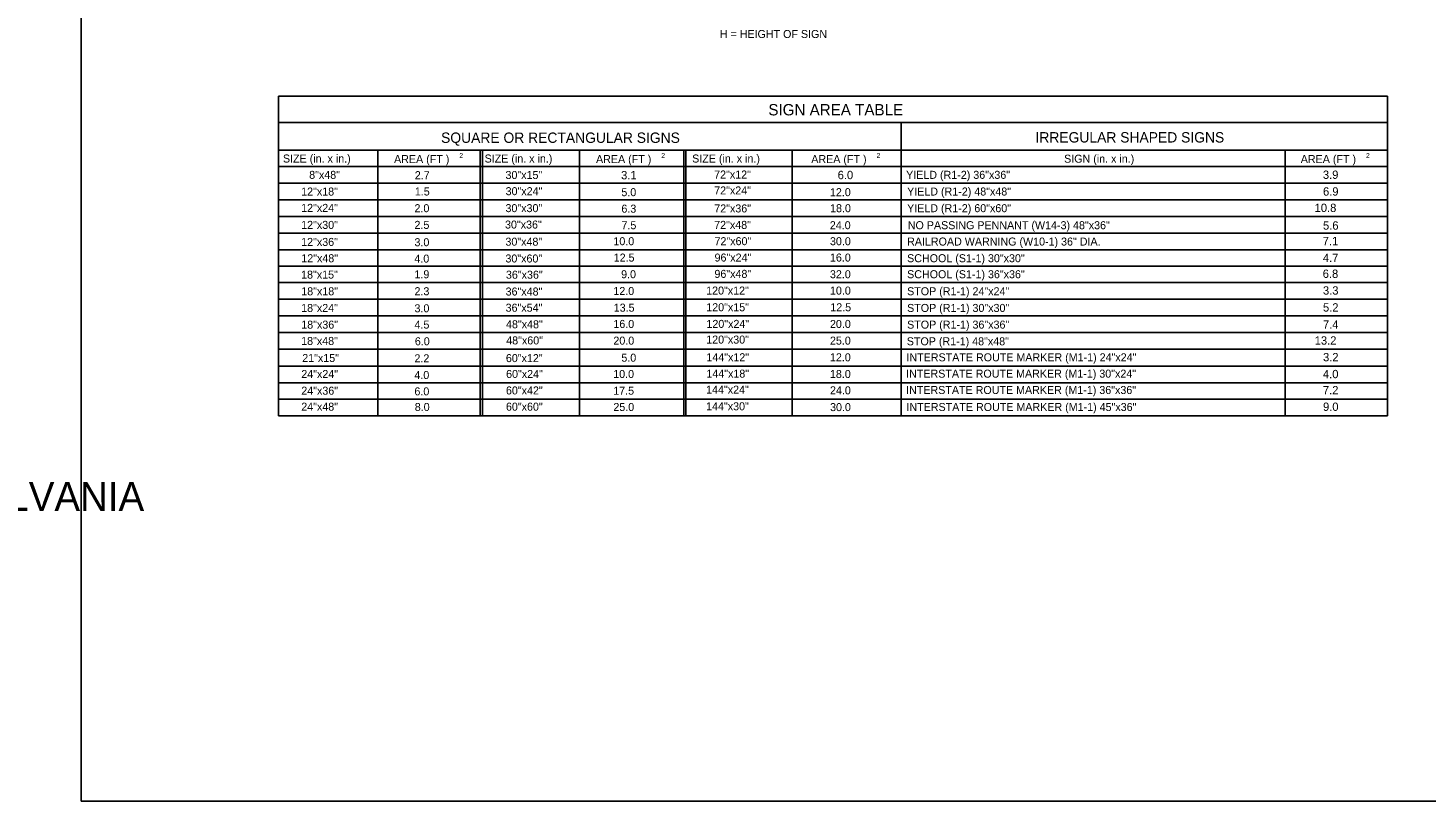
# Model space of a CAD drawing. Extents: x 644358 to 648627, y 294594 to 295782.
# Drawn here: x 645219 to 645743, y 295203 to 295492 of the extents above; entities that cross this region are included whole.
import ezdxf

# ---------------------------------------------------------------- set-up
doc = ezdxf.new("R2010")
doc.units = 0
for name, color, linetype in [('1', 7, 'Continuous'), ('2', 7, 'Continuous'), ('4', 7, 'Continuous')]:
    doc.layers.add(name, color=color, linetype=linetype)

msp = doc.modelspace()

# ---------------------------------------------------------------- linework, layer by layer
at = {"layer": '1'}
for p, q in [((645239.31, 295766.63), (645239.31, 295202.63)), ((646025.31, 295202.63), (645239.31, 295202.63)), ((645239.31, 295202.63), (645825.31, 295202.63))]:
    msp.add_line(p, q, dxfattribs=at)
at = {"layer": '2'}
for p, q in [((645313.28, 295466.78), (645313.28, 295347.03)), ((645729.03, 295466.78), (645313.28, 295466.78)), ((645729.03, 295347.03), (645729.03, 295466.78)), ((645729.03, 295456.9), (645313.28, 295456.9)), ((645546.65, 295456.9), (645546.65, 295347.03)), ((645313.28, 295446.53), (645729.03, 295446.53)), ((645350.53, 295446.53), (645350.53, 295347.03)), ((645388.9, 295446.53), (645388.9, 295347.03)), ((645389.78, 295446.53), (645389.78, 295347.03)), ((645426.08, 295446.53), (645426.08, 295347.03)), ((645465.28, 295446.53), (645465.28, 295347.03)), ((645466.03, 295446.53), (645466.03, 295347.03)), ((645505.78, 295446.53), (645505.78, 295347.03)), ((645690.65, 295347.03), (645690.65, 295446.53)), ((645313.28, 295440.4), (645729.03, 295440.4)), ((645313.28, 295434.15), (645729.03, 295434.15)), ((645313.28, 295427.9), (645729.03, 295427.9)), ((645313.28, 295421.65), (645729.03, 295421.65)), ((645313.28, 295415.4), (645729.03, 295415.4)), ((645313.28, 295409.15), (645729.03, 295409.15)), ((645313.28, 295403.03), (645729.03, 295403.03)), ((645313.28, 295396.9), (645729.03, 295396.9)), ((645313.28, 295390.65), (645729.03, 295390.65)), ((645313.28, 295384.4), (645729.03, 295384.4)), ((645313.28, 295378.15), (645729.03, 295378.15)), ((645313.28, 295371.9), (645729.03, 295371.9)), ((645313.28, 295365.65), (645729.03, 295365.65)), ((645546.65, 295365.65), (645729.03, 295365.65)), ((645313.28, 295359.4), (645729.03, 295359.4)), ((645729.03, 295359.4), (645546.65, 295359.4)), ((645313.28, 295353.28), (645729.03, 295353.28)), ((645313.28, 295347.03), (645546.65, 295347.03)), ((645729.03, 295347.03), (645546.65, 295347.03))]:
    msp.add_line(p, q, dxfattribs=at)
at = {"layer": '4'}
for p, q in [((645367.73, 295360.9), (645367.73, 295360.9)), ((645367.73, 295354.65), (645367.73, 295354.65)), ((645367.73, 295348.4), (645367.73, 295348.4))]:
    msp.add_line(p, q, dxfattribs=at)

# ---------------------------------------------------------------- texts
at = {"layer": '1'}
msp.add_text('COMMONWEALTH OF PENNSYLVANIA', height=10.7828, dxfattribs=at).set_placement((644996.9, 295311.36))
at = {"layer": '4'}
for s, height, p in [('                     H = HEIGHT OF SIGN', 3, (645455.29, 295488.57)), ('SIGN AREA TABLE', 4.25, (645496.91, 295459.57)), ('SQUARE OR RECTANGULAR SIGNS', 3.8872, (645374.2, 295449.26)), ('IRREGULAR SHAPED SIGNS', 3.8872, (645597.06, 295449.4)), ('SIZE (in. x in.)', 3, (645314.91, 295441.9)), ('AREA (FT )', 3, (645356.58, 295441.7)), ('2', 1.8, (645381.07, 295443.66)), ('SIZE (in. x in.)', 3, (645390.52, 295441.9)), ('AREA (FT )', 3, (645432.3, 295441.7)), ('2', 1.8, (645456.79, 295443.66)), ('SIZE (in. x in.)', 3, (645468.34, 295441.9)), ('AREA (FT )', 3, (645513, 295441.7)), ('2', 1.8, (645537.49, 295443.66)), ('SIGN (in. x in.)', 3, (645607.79, 295441.83)), ('AREA (FT )', 3, (645696.52, 295441.7)), ('2', 1.8, (645721.01, 295443.66)), ('8"x48"', 3, (645324.75, 295435.78)), ('30"x15"', 3, (645398.35, 295435.74)), ('3.1', 3.125, (645441.7, 295435.61)), ('72"x12"', 3, (645476.59, 295435.91)), ('6.0', 3.125, (645522.9, 295435.67)), ('YIELD (R1-2) 36"x36" ', 3, (645548.56, 295435.79)), ('3.9', 3.125, (645704.82, 295435.77)), ('2.7', 3, (645364.35, 295435.66)), ('12"x18"', 3, (645321.75, 295429.53)), ('1.5', 3, (645364.37, 295429.55)), ('30"x24"', 3, (645398.4, 295429.66)), ('5.0', 3, (645441.8, 295429.29)), ('72"x24"', 3, (645476.61, 295429.94)), ('12.0', 3, (645520, 295429.29)), ('YIELD (R1-2) 48"x48" ', 3, (645548.93, 295429.54)), ('6.9', 3.125, (645704.86, 295429.49)), ('12"x24"', 3, (645321.75, 295423.4)), ('2.0', 3, (645364.24, 295423.28)), ('30"x30"', 3, (645398.35, 295423.31)), ('6.3', 3, (645441.81, 295423.11)), ('72"x36"', 3, (645476.63, 295423.2)), ('18.0', 3, (645520.05, 295423.29)), ('YIELD (R1-2) 60"x60" ', 3, (645548.93, 295423.29)), ('10.8', 3.125, (645701.73, 295423.36)), ('12"x30"', 3, (645321.75, 295417.03)), ('2.5', 3, (645364.24, 295417.04)), ('30"x36"', 3, (645398.18, 295417.16)), ('7.5', 3, (645441.84, 295416.91)), ('72"x48"', 3, (645476.6, 295417.03)), ('24.0', 3, (645519.96, 295416.91)), ('NO PASSING PENNANT (W14-3) 48"x36" ', 3, (645549.18, 295416.91)), ('5.6', 3.125, (645704.87, 295416.74)), ('12"x36"', 3, (645321.75, 295410.65)), ('3.0', 3, (645364.23, 295410.53)), ('30"x48"', 3, (645398.33, 295410.74)), ('10.0', 3, (645438.81, 295410.91)), ('72"x60"', 3, (645476.72, 295410.92)), ('30.0', 3, (645520.01, 295410.91)), ('RAILROAD WARNING (W10-1) 36" DIA.', 3, (645548.93, 295410.79)), ('7.1', 3.125, (645704.77, 295410.93)), ('12"x48"', 3, (645321.8, 295404.53)), ('4.0', 3, (645364.19, 295404.4)), ('30"x60"', 3, (645398.33, 295404.44)), ('12.5', 3, (645438.93, 295404.79)), ('96"x24"', 3, (645476.74, 295404.79)), ('16.0', 3, (645520, 295404.79)), ('SCHOOL (S1-1) 30"x30" ', 3, (645548.93, 295404.54)), ('4.7', 3.125, (645704.82, 295404.63)), ('18"x15"', 3, (645321.72, 295398.4)), ('1.9', 3, (645364.22, 295398.53)), ('36"x36"', 3, (645398.52, 295398.36)), ('9.0', 3, (645441.71, 295398.54)), ('96"x48"', 3, (645476.69, 295398.68)), ('32.0', 3, (645520, 295398.54)), ('SCHOOL (S1-1) 36"x36" ', 3, (645548.93, 295398.54)), ('6.8', 3.125, (645704.76, 295398.66)), ('18"x18"', 3, (645321.78, 295392.15)), ('2.3', 3, (645364.24, 295392.17)), ('36"x48"', 3, (645398.4, 295392.06)), ('12.0', 3, (645438.8, 295392.26)), ('120"x12"', 3, (645473.59, 295392.42)), ('10.0', 3, (645520.01, 295392.41)), ('STOP (R1-1) 24"x24" ', 3, (645548.93, 295392.16)), ('3.3', 3.125, (645704.85, 295392.4)), ('18"x24"', 3, (645321.75, 295385.9)), ('3.0', 3, (645364.24, 295385.78)), ('36"x54"', 3, (645398.4, 295385.99)), ('13.5', 3, (645438.93, 295386.01)), ('120"x15"', 3, (645473.63, 295386.17)), ('12.5', 3, (645520.13, 295386.16)), ('STOP (R1-1) 30"x30"', 3, (645548.93, 295385.91)), ('5.2', 3.125, (645704.86, 295386.04)), ('18"x36"', 3, (645321.78, 295379.65)), ('4.5', 3, (645364.24, 295379.67)), ('48"x48"', 3, (645398.55, 295379.79)), ('16.0', 3, (645438.8, 295379.91)), ('120"x24"', 3, (645473.69, 295379.93)), ('20.0', 3, (645520.01, 295379.91)), ('STOP (R1-1) 36"x36" ', 3, (645548.93, 295379.66)), ('7.4', 3.125, (645704.86, 295379.66)), ('18"x48"', 3, (645321.74, 295373.54)), ('6.0', 3, (645364.37, 295373.42)), ('48"x60"', 3, (645398.63, 295373.74)), ('20.0', 3, (645438.81, 295373.66)), ('120"x30"', 3, (645473.62, 295374.05)), ('25.0', 3, (645520, 295373.66)), ('STOP (R1-1) 48"x48"', 3, (645548.81, 295373.41)), ('13.2', 3.125, (645701.75, 295373.66)), ('INTERSTATE ROUTE MARKER (M1-1) 24"x24" ', 3, (645548.68, 295367.41)), ('3.2', 3.125, (645704.88, 295367.41)), ('21"x15"', 3, (645322.14, 295367.15)), ('2.2', 3, (645364.23, 295367.04)), ('60"x12"', 3, (645398.5, 295367.11)), ('5.0', 3, (645441.8, 295367.26)), ('144"x12"', 3, (645473.67, 295367.43)), ('12.0', 3, (645520, 295367.41)), ('24"x24"', 3, (645321.79, 295361.15)), ('4.0', 3, (645364.2, 295360.78)), ('60"x24"', 3, (645398.58, 295361.16)), ('10.0', 3, (645438.74, 295361.16)), ('144"x18"', 3, (645473.67, 295361.3)), ('18.0', 3, (645520, 295361.16)), ('INTERSTATE ROUTE MARKER (M1-1) 30"x24" ', 3, (645548.56, 295361.29)), ('4.0', 3.125, (645704.84, 295361.08)), ('24"x36"', 3, (645321.79, 295354.9)), ('6.0', 3, (645364.21, 295354.65)), ('60"x42"', 3, (645398.53, 295354.99)), ('17.5', 3, (645438.75, 295354.89)), ('144"x24"', 3, (645473.57, 295355.3)), ('24.0', 3, (645520.02, 295355.04)), ('INTERSTATE ROUTE MARKER (M1-1) 36"x36" ', 3, (645548.56, 295355.16)), ('7.2', 3.125, (645704.83, 295355.04)), ('24"x48"', 3, (645321.78, 295348.91)), ('8.0', 3, (645364.34, 295348.8)), ('60"x60"', 3, (645398.53, 295348.91)), ('25.0', 3, (645438.8, 295348.79)), ('144"x30"', 3, (645473.57, 295349.05)), ('30.0', 3, (645520.05, 295348.75)), ('INTERSTATE ROUTE MARKER (M1-1) 45"x36" ', 3, (645548.68, 295348.79)), ('9.0', 3.125, (645704.87, 295348.82))]:
    msp.add_text(s, height=height, dxfattribs=at).set_placement(p)

doc.saveas('drawing.dxf')
